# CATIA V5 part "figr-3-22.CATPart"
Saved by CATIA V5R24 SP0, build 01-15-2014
Part number: Part1
Bounding box of the stored display mesh (mm): x -100.656 to 120.085, y -71.941 to 77.746, z 0 to 0
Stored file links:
  D:\KAVITA\CATIA V5-6R2014 Project_ Kavita\CATIA V5-6R2014_partfiles\Exercises\figr-3-22.CATPart
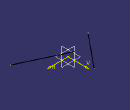
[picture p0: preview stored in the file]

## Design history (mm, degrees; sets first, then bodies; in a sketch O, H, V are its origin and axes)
Body1 (main body)
  Sketch1 on xy-plane, origin (0, 0, 0), H (1, 0, 0), V (0, 1, 0)
    line L1 (-9.7143, 77.7457) -> (-100.6564, -33.7935)
    line L2 (-27.4893, -3.1098) -> (120.0849, -71.9407)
